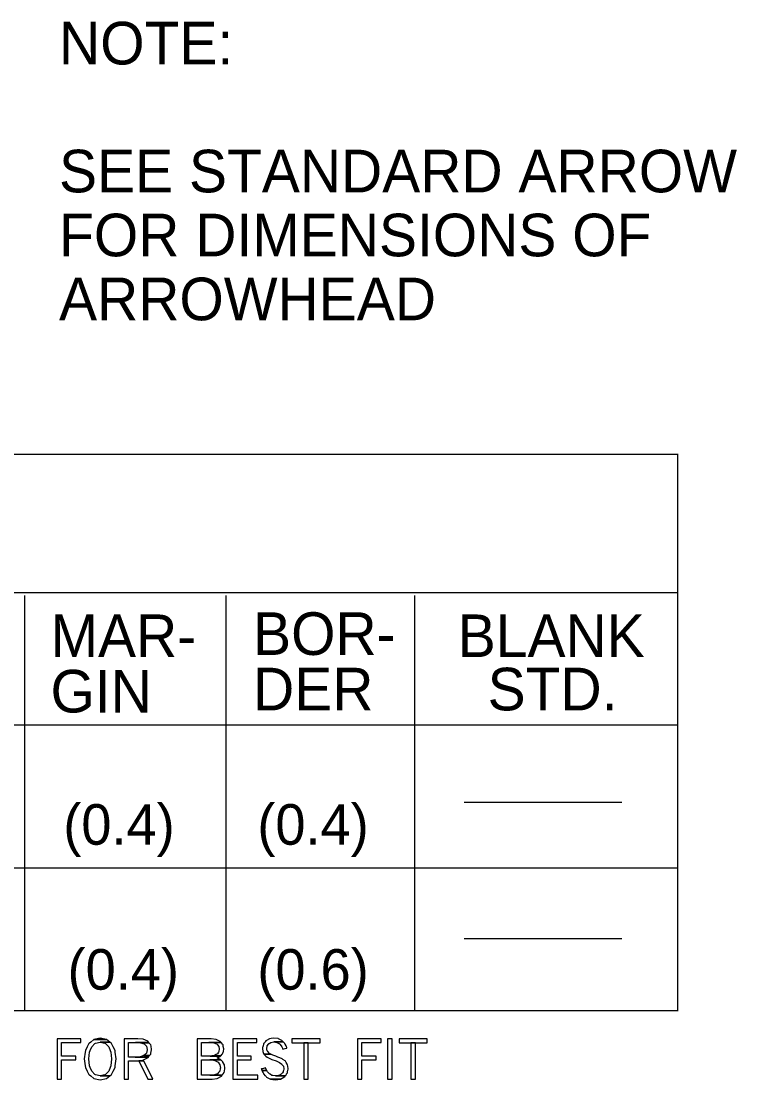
# Model space of a CAD drawing. Extents: x 0.011 to 0.188, y 0.004 to 0.261.
# Drawn here: x 0.1459 to 0.1882, y 0.0497 to 0.1123 of the extents above; entities that cross this region are included whole.
import ezdxf

# ---------------------------------------------------------------- set-up
doc = ezdxf.new("R2010")
doc.units = 0
doc.layers.add('3', color=7, linetype='Continuous')

msp = doc.modelspace()

# ---------------------------------------------------------------- linework, layer by layer
at = {"layer": '3'}
for p, q in [((0.030682, 0.086699), (0.184743, 0.086699)), ((0.184703, 0.086678), (0.184703, 0.053792)), ((0.184743, 0.078509), (0.030682, 0.078509)), ((0.146121, 0.078357), (0.146121, 0.053813)), ((0.158029, 0.078357), (0.158029, 0.053813)), ((0.169159, 0.078357), (0.169159, 0.053813)), ((0.030615, 0.070697), (0.184743, 0.070697)), ((0.172103, 0.06614), (0.181427, 0.06614)), ((0.030682, 0.062255), (0.184743, 0.062255)), ((0.172103, 0.058076), (0.181427, 0.058076)), ((0.03075, 0.053813), (0.184743, 0.053813))]:
    msp.add_line(p, q, dxfattribs=at)
for points in [[(0.14805, 0.050901), (0.14805, 0.04976), (0.148312, 0.04976), (0.148312, 0.050901), (0.149153, 0.050901), (0.149153, 0.051126), (0.148312, 0.051126), (0.148312, 0.051921), (0.149448, 0.051921), (0.149448, 0.052147), (0.14805, 0.052147), (0.14805, 0.051921), (0.14805, 0.051126)], [(0.150225, 0.049798), (0.150596, 0.049721), (0.150968, 0.049798), (0.151156, 0.049951), (0.150596, 0.049951), (0.150314, 0.050015), (0.150285, 0.050043), (0.150092, 0.050227), (0.150002, 0.050455), (0.149963, 0.050556), (0.149921, 0.050953), (0.149963, 0.05135), (0.150002, 0.051451), (0.150092, 0.051679), (0.150285, 0.051863), (0.150314, 0.051891), (0.150596, 0.051956), (0.151156, 0.051956), (0.150968, 0.052108), (0.150225, 0.052108), (0.150036, 0.051956), (0.149956, 0.051891), (0.149922, 0.051863), (0.149831, 0.051679), (0.149718, 0.051451), (0.149705, 0.05135), (0.149653, 0.050953), (0.149705, 0.050556), (0.149718, 0.050455), (0.149831, 0.050227), (0.149922, 0.050043), (0.149956, 0.050015), (0.150036, 0.049951)], [(0.150596, 0.052185), (0.150225, 0.052108), (0.150968, 0.052108)], [(0.150877, 0.050015), (0.150596, 0.049951), (0.151156, 0.049951), (0.151237, 0.050015), (0.151236, 0.050015), (0.151271, 0.050043), (0.151362, 0.050227), (0.151475, 0.050455), (0.151488, 0.050556), (0.151539, 0.050953), (0.151488, 0.05135), (0.151475, 0.051451), (0.151362, 0.051679), (0.151271, 0.051863), (0.151237, 0.051891), (0.151236, 0.051891), (0.151156, 0.051956), (0.150595, 0.051956), (0.150877, 0.051891), (0.150906, 0.051863), (0.151099, 0.051679), (0.151189, 0.051451), (0.151229, 0.05135), (0.151271, 0.050953), (0.151229, 0.050556), (0.151189, 0.050455), (0.151099, 0.050227), (0.150906, 0.050043)], [(0.152013, 0.050842), (0.152013, 0.04976), (0.152272, 0.04976), (0.152272, 0.050842), (0.15317, 0.050842), (0.15314, 0.050904), (0.153242, 0.05094), (0.153429, 0.051046), (0.153443, 0.051064), (0.152272, 0.051064), (0.152272, 0.051067), (0.152272, 0.051082), (0.152272, 0.05115), (0.152272, 0.051246), (0.152272, 0.05129), (0.152272, 0.051494), (0.152272, 0.051514), (0.152272, 0.051705), (0.152272, 0.051782), (0.152272, 0.051852), (0.152272, 0.051911), (0.152272, 0.051922), (0.152272, 0.051924), (0.153465, 0.051924), (0.153405, 0.051997), (0.153129, 0.052116), (0.152812, 0.052144), (0.152683, 0.052147), (0.152013, 0.052147), (0.152013, 0.052144), (0.152013, 0.052116), (0.152013, 0.051997), (0.152013, 0.051924), (0.152013, 0.051922), (0.152013, 0.051911), (0.152013, 0.051852), (0.152013, 0.051782), (0.152013, 0.051705), (0.152013, 0.051514), (0.152013, 0.051494), (0.152013, 0.05129), (0.152013, 0.051246), (0.152013, 0.05115), (0.152013, 0.051082), (0.152013, 0.051067), (0.152013, 0.051064), (0.152013, 0.051046), (0.152013, 0.05094), (0.152013, 0.050904)], [(0.156327, 0.049763), (0.156327, 0.04976), (0.157052, 0.04976), (0.157206, 0.049763), (0.157501, 0.049806), (0.157761, 0.049946), (0.157794, 0.04999), (0.156587, 0.04999), (0.156587, 0.049993), (0.156587, 0.050011), (0.156587, 0.050084), (0.156587, 0.05015), (0.156587, 0.050228), (0.156587, 0.050386), (0.156587, 0.050407), (0.156587, 0.0506), (0.156587, 0.050606), (0.156587, 0.050762), (0.156587, 0.050787), (0.156587, 0.050863), (0.156587, 0.050899), (0.156587, 0.050902), (0.157715, 0.050902), (0.157701, 0.050916), (0.15757, 0.05099), (0.157506, 0.051018), (0.157571, 0.051044), (0.157676, 0.051106), (0.157695, 0.051124), (0.156587, 0.051124), (0.156587, 0.05113), (0.156587, 0.051164), (0.156587, 0.051214), (0.156587, 0.051258), (0.156587, 0.05136), (0.156587, 0.051394), (0.156587, 0.051546), (0.156587, 0.051562), (0.156587, 0.051695), (0.156587, 0.051788), (0.156587, 0.051821), (0.156587, 0.051905), (0.156587, 0.051931), (0.156587, 0.051932), (0.15774, 0.051932), (0.15769, 0.051995), (0.157445, 0.052106), (0.157152, 0.052144), (0.156973, 0.052147), (0.156327, 0.052147), (0.156327, 0.052144), (0.156327, 0.052106), (0.156327, 0.051995), (0.156327, 0.051932), (0.156327, 0.051931), (0.156327, 0.051905), (0.156327, 0.051821), (0.156327, 0.051788), (0.156327, 0.051695), (0.156327, 0.051562), (0.156327, 0.051546), (0.156327, 0.051394), (0.156327, 0.05136), (0.156327, 0.051258), (0.156327, 0.051214), (0.156327, 0.051164), (0.156327, 0.05113), (0.156327, 0.051124), (0.156327, 0.051106), (0.156327, 0.051044), (0.156327, 0.051018), (0.156327, 0.05099), (0.156327, 0.050916), (0.156327, 0.050902), (0.156327, 0.050899), (0.156327, 0.050863), (0.156327, 0.050787), (0.156327, 0.050762), (0.156327, 0.050606), (0.156327, 0.0506), (0.156327, 0.050407), (0.156327, 0.050386), (0.156327, 0.050228), (0.156327, 0.05015), (0.156327, 0.050084), (0.156327, 0.050011), (0.156327, 0.049993), (0.156327, 0.04999), (0.156327, 0.049946), (0.156327, 0.049806)], [(0.158442, 0.04999), (0.158442, 0.04976), (0.159905, 0.04976), (0.159905, 0.04999), (0.158704, 0.04999), (0.158704, 0.050903), (0.159516, 0.050903), (0.159516, 0.051124), (0.158704, 0.051124), (0.158704, 0.051921), (0.159849, 0.051921), (0.159849, 0.052147), (0.158442, 0.052147), (0.158442, 0.051921), (0.158442, 0.051124), (0.158442, 0.050903)], [(0.16025, 0.051283), (0.160272, 0.051233), (0.160687, 0.051233), (0.160591, 0.051283), (0.160502, 0.051388), (0.160469, 0.051427), (0.160446, 0.051533), (0.160437, 0.051574), (0.160442, 0.051602), (0.160445, 0.051624), (0.160454, 0.051674), (0.160455, 0.05168), (0.160463, 0.051728), (0.160533, 0.051834), (0.160545, 0.051852), (0.160556, 0.051859), (0.160572, 0.051869), (0.160682, 0.051936), (0.160685, 0.051937), (0.160855, 0.051964), (0.161413, 0.051964), (0.161355, 0.052026), (0.161335, 0.052047), (0.161135, 0.052143), (0.161103, 0.052158), (0.160849, 0.052185), (0.160848, 0.052185), (0.160691, 0.052158), (0.160602, 0.052143), (0.16043, 0.052047), (0.160392, 0.052026), (0.160341, 0.051964), (0.16032, 0.051937), (0.160318, 0.051936), (0.160263, 0.051869), (0.160255, 0.051859), (0.160253, 0.051852), (0.160248, 0.051834), (0.160217, 0.051728), (0.160202, 0.05168), (0.160201, 0.051674), (0.160186, 0.051624), (0.160187, 0.051602), (0.160189, 0.051574), (0.160192, 0.051533), (0.160199, 0.051427), (0.160202, 0.051388)], [(0.161374, 0.051574), (0.16139, 0.051533), (0.161531, 0.051574), (0.161628, 0.051602), (0.161621, 0.051624), (0.161605, 0.051674), (0.161603, 0.05168), (0.161578, 0.051728), (0.161522, 0.051834), (0.161513, 0.051852), (0.161509, 0.051859), (0.161504, 0.051869), (0.16144, 0.051936), (0.161439, 0.051937), (0.161413, 0.051964), (0.160854, 0.051964), (0.161027, 0.051937), (0.161037, 0.051936), (0.161155, 0.051869), (0.161173, 0.051859), (0.161185, 0.051852), (0.161218, 0.051834), (0.161295, 0.051728), (0.161331, 0.05168), (0.161336, 0.051674), (0.161355, 0.051624), (0.161363, 0.051602)], [(0.161925, 0.052147), (0.161925, 0.051917), (0.163587, 0.051917), (0.163587, 0.052147)], [(0.165791, 0.050901), (0.165791, 0.04976), (0.166053, 0.04976), (0.166053, 0.050901), (0.166895, 0.050901), (0.166895, 0.051126), (0.166053, 0.051126), (0.166053, 0.051921), (0.167189, 0.051921), (0.167189, 0.052147), (0.165791, 0.052147), (0.165791, 0.051921), (0.165791, 0.051126)], [(0.167578, 0.052147), (0.167578, 0.04976), (0.167845, 0.04976), (0.167845, 0.052147)], [(0.168255, 0.052147), (0.168255, 0.051917), (0.169917, 0.051917), (0.169917, 0.052147)], [(0.152791, 0.051922), (0.152979, 0.051911), (0.153477, 0.051911), (0.153467, 0.051922), (0.153467, 0.051922), (0.153465, 0.051924), (0.15268, 0.051924)], [(0.153278, 0.051246), (0.153179, 0.05115), (0.15351, 0.05115), (0.153584, 0.051246), (0.153593, 0.05129), (0.153632, 0.051494), (0.153636, 0.051514), (0.153599, 0.051705), (0.153584, 0.051782), (0.153526, 0.051852), (0.153477, 0.051911), (0.152978, 0.051911), (0.153186, 0.051852), (0.153253, 0.051782), (0.153328, 0.051705), (0.153365, 0.051514), (0.153369, 0.051494), (0.153324, 0.05129)], [(0.157022, 0.051932), (0.157123, 0.051931), (0.15774, 0.051931), (0.15774, 0.051932)], [(0.157359, 0.051164), (0.157191, 0.05113), (0.157701, 0.05113), (0.157737, 0.051164), (0.15779, 0.051214), (0.157814, 0.051258), (0.15787, 0.05136), (0.157875, 0.051394), (0.157874, 0.051394), (0.157895, 0.051546), (0.157898, 0.051562), (0.157871, 0.051695), (0.157853, 0.051788), (0.157827, 0.051821), (0.157761, 0.051905), (0.15774, 0.051931), (0.157123, 0.051931), (0.15732, 0.051905), (0.157507, 0.051821), (0.157531, 0.051788), (0.157601, 0.051695), (0.157627, 0.051562), (0.15763, 0.051546), (0.157608, 0.051394), (0.157587, 0.05136), (0.157522, 0.051258), (0.157446, 0.051214)], [(0.16262, 0.051917), (0.16262, 0.04976), (0.162891, 0.04976), (0.162891, 0.051917)], [(0.16895, 0.051917), (0.16895, 0.04976), (0.16922, 0.04976), (0.16922, 0.051917)], [(0.152757, 0.051067), (0.152671, 0.051064), (0.153443, 0.051064), (0.153446, 0.051067), (0.153457, 0.051082), (0.15351, 0.05115), (0.153178, 0.05115), (0.152961, 0.051082)], [(0.152886, 0.050842), (0.153409, 0.04976), (0.1537, 0.04976), (0.15317, 0.050842)], [(0.157343, 0.050011), (0.157169, 0.049993), (0.157796, 0.049993), (0.15781, 0.050011), (0.157865, 0.050084), (0.157915, 0.05015), (0.157931, 0.050228), (0.157964, 0.050386), (0.157961, 0.050407), (0.157935, 0.0506), (0.157934, 0.050606), (0.15785, 0.050762), (0.157837, 0.050787), (0.157756, 0.050863), (0.157718, 0.050899), (0.157715, 0.050902), (0.157077, 0.050902), (0.157196, 0.050899), (0.157378, 0.050863), (0.157517, 0.050787), (0.157561, 0.050762), (0.157668, 0.050606), (0.157672, 0.0506), (0.157695, 0.050407), (0.157691, 0.050386), (0.157657, 0.050228), (0.157588, 0.05015), (0.15753, 0.050084)], [(0.15719, 0.05113), (0.157095, 0.051124), (0.157695, 0.051124), (0.157701, 0.05113)], [(0.161137, 0.049974), (0.160946, 0.049949), (0.161533, 0.049949), (0.16155, 0.049974), (0.161556, 0.049984), (0.161602, 0.050054), (0.161612, 0.050069), (0.161612, 0.050069), (0.161624, 0.050087), (0.161657, 0.050136), (0.161666, 0.050191), (0.161672, 0.050224), (0.161679, 0.050264), (0.161694, 0.050349), (0.161695, 0.050359), (0.161696, 0.050364), (0.161699, 0.050381), (0.161678, 0.05052), (0.161664, 0.050616), (0.161645, 0.050648), (0.161582, 0.050751), (0.161541, 0.050819), (0.161517, 0.050836), (0.161387, 0.050931), (0.161344, 0.050963), (0.161219, 0.051016), (0.1611, 0.051068), (0.160979, 0.051111), (0.160798, 0.051177), (0.160687, 0.051233), (0.160272, 0.051233), (0.160324, 0.051177), (0.160385, 0.051111), (0.160454, 0.051068), (0.160534, 0.051016), (0.160656, 0.050963), (0.16073, 0.050931), (0.160988, 0.050836), (0.161026, 0.050819), (0.161185, 0.050751), (0.161338, 0.050648), (0.161358, 0.050616), (0.16142, 0.05052), (0.161441, 0.050381), (0.161444, 0.050364), (0.161442, 0.050359), (0.16144, 0.050349), (0.161423, 0.050264), (0.161414, 0.050224), (0.161408, 0.050191), (0.161363, 0.050136), (0.161323, 0.050087), (0.161308, 0.050069), (0.161296, 0.050054), (0.161157, 0.049984)], [(0.160119, 0.050349), (0.16015, 0.050264), (0.160438, 0.050264), (0.160394, 0.050349), (0.160391, 0.050359), (0.160389, 0.050364), (0.160384, 0.050381), (0.160384, 0.050381), (0.160365, 0.050439), (0.160365, 0.050439), (0.160184, 0.050381), (0.160132, 0.050364), (0.160116, 0.050359)], [(0.160427, 0.049882), (0.160657, 0.049765), (0.161253, 0.049765), (0.161451, 0.049882), (0.161513, 0.049918), (0.161533, 0.049949), (0.160946, 0.049949), (0.160803, 0.049974), (0.160803, 0.049974), (0.160747, 0.049984), (0.160633, 0.050054), (0.160609, 0.050069), (0.160579, 0.050087), (0.160536, 0.050136), (0.160488, 0.050191), (0.160487, 0.050191), (0.160459, 0.050224), (0.160438, 0.050264), (0.16015, 0.050264), (0.16017, 0.050224), (0.160188, 0.050191), (0.160216, 0.050136), (0.160241, 0.050087), (0.160251, 0.050069), (0.160264, 0.050054), (0.160331, 0.049984), (0.16034, 0.049974), (0.160364, 0.049949), (0.160393, 0.049918)], [(0.157169, 0.049993), (0.157078, 0.04999), (0.157794, 0.04999), (0.157796, 0.049993)], [(0.160662, 0.049764), (0.160939, 0.049721), (0.161252, 0.049764), (0.161253, 0.049765), (0.160657, 0.049765)]]:
    msp.add_lwpolyline(points, close=True, dxfattribs=at)

# ---------------------------------------------------------------- texts
for s, height, p in [('NOTE:', 0.0025197, (0.148163, 0.109736)), ('SEE STANDARD ARROW', 0.00251975, (0.148163, 0.102176)), ('FOR DIMENSIONS OF', 0.00251975, (0.148163, 0.098396)), ('ARROWHEAD', 0.0025197, (0.148163, 0.094616)), ('MAR-', 0.0025197, (0.147659, 0.074708)), ('BOR-', 0.0025197, (0.159629, 0.074834)), ('BLANK', 0.0025197, (0.171725, 0.074708)), ('GIN', 0.0025197, (0.147659, 0.071432)), ('DER', 0.0025197, (0.159629, 0.071558)), ('STD.', 0.0025197, (0.173489, 0.071558)), ('(0.4)', 0.0023943, (0.148415, 0.06362)), ('(0.4)', 0.0023943, (0.159881, 0.06362)), ('(0.4)', 0.0023943, (0.148667, 0.055052)), ('(0.6)', 0.0023943, (0.159881, 0.055052))]:
    msp.add_text(s, height=height, dxfattribs=at).set_placement(p)

doc.saveas('drawing.dxf')
